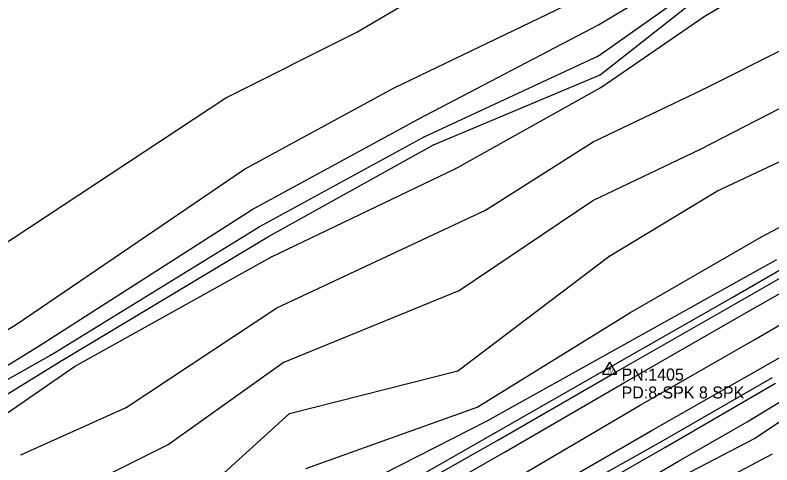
# Model space of a CAD drawing. Extents: x 1419505 to 1434054, y 1956910 to 1968644.
# Drawn here: x 1420049.5 to 1420365.7, y 1957354.8 to 1957542.8 of the extents above; entities that cross this region are included whole.
import ezdxf

# ---------------------------------------------------------------- set-up
doc = ezdxf.new("R2010")
doc.units = 0
for name, color, linetype in [('S_BREAKLINE', 7, 'Continuous'), ('S_DITCHLINE', 7, 'Continuous'), ('S_EDGE_PAVEMENT', 7, 'Continuous'), ('S_GRD_PT_SYM', 7, 'Continuous'), ('S_PAVEMENT_CROWN', 7, 'Continuous'), ('S_RDW_PT_SYM', 7, 'Continuous'), ('S_SECONDARY_CTL', 7, 'Continuous'), ('S_SECONDARY_CTL_ANNOT', 7, 'Continuous'), ('S_SHOULDER', 7, 'Continuous')]:
    doc.layers.add(name, color=color, linetype=linetype)

msp = doc.modelspace()

# ---------------------------------------------------------------- linework, layer by layer
at = {"layer": 'S_BREAKLINE'}
for p, q in [((1420192.3036, 1957535.6307), (1420290.752, 1957593.9905)), ((1420337.512, 1957542.1811), (1420418.3802, 1957590.8533)), ((1420293.3101, 1957538.7059), (1420365.5308, 1957582.2917)), ((1420336.8469, 1957511.6521), (1420430.621, 1957558.8422)), ((1420207.9006, 1957512.3842), (1420293.4111, 1957553.6049)), ((1420294.2222, 1957512.5972), (1420337.512, 1957542.1811)), ((1420335.9639, 1957486.7575), (1420440.9487, 1957541.147)), ((1420218.2373, 1957499.4904), (1420293.3101, 1957538.7059)), ((1420137.6381, 1957508.2519), (1420192.3036, 1957535.6307)), ((1420342.7853, 1957469.2664), (1420453.1484, 1957521.3868)), ((1420145.4236, 1957478.459), (1420207.9006, 1957512.3842)), ((1420233.6373, 1957478.746), (1420294.2222, 1957512.5972)), ((1420291.051, 1957489.8917), (1420336.8469, 1957511.6521)), ((1420022.9537, 1957432.616), (1420137.6381, 1957508.2519)), ((1420361.3455, 1957450.0972), (1420459.9679, 1957502.9656)), ((1420148.5408, 1957461.4819), (1420218.2373, 1957499.4904)), ((1420246.1361, 1957461.2649), (1420291.051, 1957489.8917)), ((1420290.916, 1957465.2691), (1420335.9639, 1957486.7575)), ((1420049.6074, 1957413.2558), (1420145.4236, 1957478.459)), ((1420156.6193, 1957441.7066), (1420233.6373, 1957478.746)), ((1420297.5794, 1957441.9206), (1420342.7853, 1957469.2664)), ((1420235.1024, 1957427.7497), (1420290.916, 1957465.2691)), ((1420059.534, 1957404.5312), (1420148.5408, 1957461.4819)), ((1420158.9444, 1957420.4363), (1420246.1361, 1957461.2649)), ((1420349.1857, 1957424.8305), (1420395.4067, 1957451.5023)), ((1420306.415, 1957418.4231), (1420361.3455, 1957450.0972)), ((1420074.324, 1957395.9717), (1420156.6193, 1957441.7066)), ((1420234.4453, 1957394.0666), (1420297.5794, 1957441.9206)), ((1420246.7721, 1957373.2022), (1420367.7909, 1957440.5896)), ((1420161.4816, 1957397.5688), (1420235.1024, 1957427.7497)), ((1420299.3175, 1957396.3807), (1420349.1857, 1957424.8305)), ((1420095.8914, 1957378.8396), (1420158.9444, 1957420.4363)), ((1420242.6288, 1957378.8926), (1420306.415, 1957418.4231)), ((1420024.8008, 1957398.6088), (1420049.6074, 1957413.2558)), ((1420021.9566, 1957381.6337), (1420059.534, 1957404.5312)), ((1420113.5025, 1957363.3696), (1420161.4816, 1957397.5688)), ((1420042.6259, 1957374.0053), (1420074.324, 1957395.9717)), ((1420164.2098, 1957376.2314), (1420234.4453, 1957394.0666)), ((1420249.9023, 1957368.1239), (1420299.3175, 1957396.3807)), ((1420320.9429, 1957362.0845), (1420367.2719, 1957388.9172)), ((1420355.4481, 1957372.7822), (1420378.5366, 1957386.9371)), ((1420358.5423, 1957365.7937), (1420382.7719, 1957382.3268)), ((1420051.9785, 1957359.0183), (1420095.8914, 1957378.8396)), ((1420171.0272, 1957353.2939), (1420242.6288, 1957378.8926)), ((1420127.9904, 1957343.5183), (1420164.2098, 1957376.2314)), ((1420178.1397, 1957338.305), (1420246.7721, 1957373.2022)), ((1420326.7323, 1957356.3401), (1420355.4481, 1957372.7822)), ((1420195.6758, 1957337.1809), (1420249.9023, 1957368.1239)), ((1420328.5074, 1957350.2417), (1420358.5423, 1957365.7937)), ((1420058.3479, 1957335.8728), (1420113.5025, 1957363.3696)), ((1420268.5635, 1957332.1216), (1420320.9429, 1957362.0845)), ((1420331.7176, 1957341.3011), (1420365.9838, 1957359.4623)), ((1420293.5931, 1957337.1349), (1420326.7323, 1957356.3401))]:
    msp.add_line(p, q, dxfattribs=at)
at = {"layer": 'S_DITCHLINE'}
for p, q in [((1420293.3431, 1957525.8091), (1420350.8378, 1957566.4497)), ((1420294.0512, 1957517.8655), (1420350.0148, 1957561.9554)), ((1420220.4114, 1957491.8719), (1420293.3431, 1957525.8091)), ((1420224.2847, 1957488.5137), (1420294.0512, 1957517.8655)), ((1420151.461, 1957454.2804), (1420220.4114, 1957491.8719)), ((1420155.4362, 1957450.2852), (1420224.2847, 1957488.5137)), ((1420064.5173, 1957400.875), (1420151.461, 1957454.2804)), ((1420068.3256, 1957397.9718), (1420155.4362, 1957450.2852)), ((1420022.8927, 1957377.2905), (1420064.5173, 1957400.875)), ((1420027.818, 1957373.1632), (1420068.3256, 1957397.9718))]:
    msp.add_line(p, q, dxfattribs=at)
at = {"layer": 'S_EDGE_PAVEMENT'}
for p, q in [((1420352.896, 1957417.206), (1420400.517, 1957444.3878)), ((1420364.1637, 1957396.8567), (1420413.3409, 1957425.0856)), ((1420304.2138, 1957389.2652), (1420352.896, 1957417.206)), ((1420316.0416, 1957369.443), (1420364.1637, 1957396.8567)), ((1420254.2766, 1957360.2364), (1420304.2138, 1957389.2652)), ((1420265.1203, 1957340.1861), (1420316.0416, 1957369.443)), ((1420200.5981, 1957329.8654), (1420254.2766, 1957360.2364))]:
    msp.add_line(p, q, dxfattribs=at)
at = {"layer": 'S_GRD_PT_SYM'}
for points in [[(1420337.512, 1957542.1811), (1420337.512, 1957542.2311), (1420337.512, 1957542.1811), (1420337.462, 1957542.1811), (1420337.512, 1957542.1811), (1420337.512, 1957542.1311), (1420337.512, 1957542.1811), (1420337.562, 1957542.1811)], [(1420293.3101, 1957538.7059), (1420293.3101, 1957538.7559), (1420293.3101, 1957538.7059), (1420293.2601, 1957538.7059), (1420293.3101, 1957538.7059), (1420293.3101, 1957538.6559), (1420293.3101, 1957538.7059), (1420293.3601, 1957538.7059)], [(1420192.3036, 1957535.6307), (1420192.3036, 1957535.6807), (1420192.3036, 1957535.6307), (1420192.2536, 1957535.6307), (1420192.3036, 1957535.6307), (1420192.3036, 1957535.5807), (1420192.3036, 1957535.6307), (1420192.3536, 1957535.6307)], [(1420293.3431, 1957525.8091), (1420293.3431, 1957525.8591), (1420293.3431, 1957525.8091), (1420293.2931, 1957525.8091), (1420293.3431, 1957525.8091), (1420293.3431, 1957525.7591), (1420293.3431, 1957525.8091), (1420293.3931, 1957525.8091)], [(1420294.0512, 1957517.8655), (1420294.0512, 1957517.9155), (1420294.0512, 1957517.8655), (1420294.0012, 1957517.8655), (1420294.0512, 1957517.8655), (1420294.0512, 1957517.8155), (1420294.0512, 1957517.8655), (1420294.1012, 1957517.8655)], [(1420207.9006, 1957512.3842), (1420207.9006, 1957512.4342), (1420207.9006, 1957512.3842), (1420207.8506, 1957512.3842), (1420207.9006, 1957512.3842), (1420207.9006, 1957512.3342), (1420207.9006, 1957512.3842), (1420207.9506, 1957512.3842)], [(1420294.2222, 1957512.5972), (1420294.2222, 1957512.6472), (1420294.2222, 1957512.5972), (1420294.1722, 1957512.5972), (1420294.2222, 1957512.5972), (1420294.2222, 1957512.5472), (1420294.2222, 1957512.5972), (1420294.2722, 1957512.5972)], [(1420336.8469, 1957511.6521), (1420336.8469, 1957511.7021), (1420336.8469, 1957511.6521), (1420336.7969, 1957511.6521), (1420336.8469, 1957511.6521), (1420336.8469, 1957511.6021), (1420336.8469, 1957511.6521), (1420336.8969, 1957511.6521)], [(1420137.6381, 1957508.2519), (1420137.6381, 1957508.3019), (1420137.6381, 1957508.2519), (1420137.5881, 1957508.2519), (1420137.6381, 1957508.2519), (1420137.6381, 1957508.2019), (1420137.6381, 1957508.2519), (1420137.6881, 1957508.2519)], [(1420218.2373, 1957499.4904), (1420218.2373, 1957499.5404), (1420218.2373, 1957499.4904), (1420218.1873, 1957499.4904), (1420218.2373, 1957499.4904), (1420218.2373, 1957499.4404), (1420218.2373, 1957499.4904), (1420218.2873, 1957499.4904)], [(1420220.4114, 1957491.8719), (1420220.4114, 1957491.9219), (1420220.4114, 1957491.8719), (1420220.3614, 1957491.8719), (1420220.4114, 1957491.8719), (1420220.4114, 1957491.8219), (1420220.4114, 1957491.8719), (1420220.4614, 1957491.8719)], [(1420291.051, 1957489.8917), (1420291.051, 1957489.9417), (1420291.051, 1957489.8917), (1420291.001, 1957489.8917), (1420291.051, 1957489.8917), (1420291.051, 1957489.8417), (1420291.051, 1957489.8917), (1420291.101, 1957489.8917)], [(1420224.2847, 1957488.5137), (1420224.2847, 1957488.5637), (1420224.2847, 1957488.5137), (1420224.2347, 1957488.5137), (1420224.2847, 1957488.5137), (1420224.2847, 1957488.4637), (1420224.2847, 1957488.5137), (1420224.3347, 1957488.5137)], [(1420335.9639, 1957486.7575), (1420335.9639, 1957486.8075), (1420335.9639, 1957486.7575), (1420335.9139, 1957486.7575), (1420335.9639, 1957486.7575), (1420335.9639, 1957486.7075), (1420335.9639, 1957486.7575), (1420336.0139, 1957486.7575)], [(1420145.4236, 1957478.459), (1420145.4236, 1957478.509), (1420145.4236, 1957478.459), (1420145.3736, 1957478.459), (1420145.4236, 1957478.459), (1420145.4236, 1957478.409), (1420145.4236, 1957478.459), (1420145.4736, 1957478.459)], [(1420233.6373, 1957478.746), (1420233.6373, 1957478.796), (1420233.6373, 1957478.746), (1420233.5873, 1957478.746), (1420233.6373, 1957478.746), (1420233.6373, 1957478.696), (1420233.6373, 1957478.746), (1420233.6873, 1957478.746)], [(1420342.7853, 1957469.2664), (1420342.7853, 1957469.3164), (1420342.7853, 1957469.2664), (1420342.7353, 1957469.2664), (1420342.7853, 1957469.2664), (1420342.7853, 1957469.2164), (1420342.7853, 1957469.2664), (1420342.8353, 1957469.2664)], [(1420290.916, 1957465.2691), (1420290.916, 1957465.3191), (1420290.916, 1957465.2691), (1420290.866, 1957465.2691), (1420290.916, 1957465.2691), (1420290.916, 1957465.2191), (1420290.916, 1957465.2691), (1420290.966, 1957465.2691)], [(1420148.5408, 1957461.4819), (1420148.5408, 1957461.5319), (1420148.5408, 1957461.4819), (1420148.4908, 1957461.4819), (1420148.5408, 1957461.4819), (1420148.5408, 1957461.4319), (1420148.5408, 1957461.4819), (1420148.5908, 1957461.4819)], [(1420246.1361, 1957461.2649), (1420246.1361, 1957461.3149), (1420246.1361, 1957461.2649), (1420246.0861, 1957461.2649), (1420246.1361, 1957461.2649), (1420246.1361, 1957461.2149), (1420246.1361, 1957461.2649), (1420246.1861, 1957461.2649)], [(1420151.461, 1957454.2804), (1420151.461, 1957454.3304), (1420151.461, 1957454.2804), (1420151.411, 1957454.2804), (1420151.461, 1957454.2804), (1420151.461, 1957454.2304), (1420151.461, 1957454.2804), (1420151.511, 1957454.2804)], [(1420155.4362, 1957450.2852), (1420155.4362, 1957450.3352), (1420155.4362, 1957450.2852), (1420155.3862, 1957450.2852), (1420155.4362, 1957450.2852), (1420155.4362, 1957450.2352), (1420155.4362, 1957450.2852), (1420155.4862, 1957450.2852)], [(1420361.3455, 1957450.0972), (1420361.3455, 1957450.1472), (1420361.3455, 1957450.0972), (1420361.2955, 1957450.0972), (1420361.3455, 1957450.0972), (1420361.3455, 1957450.0472), (1420361.3455, 1957450.0972), (1420361.3955, 1957450.0972)], [(1420156.6193, 1957441.7066), (1420156.6193, 1957441.7566), (1420156.6193, 1957441.7066), (1420156.5693, 1957441.7066), (1420156.6193, 1957441.7066), (1420156.6193, 1957441.6566), (1420156.6193, 1957441.7066), (1420156.6693, 1957441.7066)], [(1420297.5794, 1957441.9206), (1420297.5794, 1957441.9706), (1420297.5794, 1957441.9206), (1420297.5294, 1957441.9206), (1420297.5794, 1957441.9206), (1420297.5794, 1957441.8706), (1420297.5794, 1957441.9206), (1420297.6294, 1957441.9206)], [(1420235.1024, 1957427.7497), (1420235.1024, 1957427.7997), (1420235.1024, 1957427.7497), (1420235.0524, 1957427.7497), (1420235.1024, 1957427.7497), (1420235.1024, 1957427.6997), (1420235.1024, 1957427.7497), (1420235.1524, 1957427.7497)], [(1420349.1857, 1957424.8305), (1420349.1857, 1957424.8805), (1420349.1857, 1957424.8305), (1420349.1357, 1957424.8305), (1420349.1857, 1957424.8305), (1420349.1857, 1957424.7805), (1420349.1857, 1957424.8305), (1420349.2357, 1957424.8305)], [(1420158.9444, 1957420.4363), (1420158.9444, 1957420.4863), (1420158.9444, 1957420.4363), (1420158.8944, 1957420.4363), (1420158.9444, 1957420.4363), (1420158.9444, 1957420.3863), (1420158.9444, 1957420.4363), (1420158.9944, 1957420.4363)], [(1420306.415, 1957418.4231), (1420306.415, 1957418.4731), (1420306.415, 1957418.4231), (1420306.365, 1957418.4231), (1420306.415, 1957418.4231), (1420306.415, 1957418.3731), (1420306.415, 1957418.4231), (1420306.465, 1957418.4231)], [(1420049.6074, 1957413.2558), (1420049.6074, 1957413.3058), (1420049.6074, 1957413.2558), (1420049.5574, 1957413.2558), (1420049.6074, 1957413.2558), (1420049.6074, 1957413.2058), (1420049.6074, 1957413.2558), (1420049.6574, 1957413.2558)], [(1420059.534, 1957404.5312), (1420059.534, 1957404.5812), (1420059.534, 1957404.5312), (1420059.484, 1957404.5312), (1420059.534, 1957404.5312), (1420059.534, 1957404.4812), (1420059.534, 1957404.5312), (1420059.584, 1957404.5312)], [(1420064.5173, 1957400.875), (1420064.5173, 1957400.925), (1420064.5173, 1957400.875), (1420064.4673, 1957400.875), (1420064.5173, 1957400.875), (1420064.5173, 1957400.825), (1420064.5173, 1957400.875), (1420064.5673, 1957400.875)], [(1420068.3256, 1957397.9718), (1420068.3256, 1957398.0218), (1420068.3256, 1957397.9718), (1420068.2756, 1957397.9718), (1420068.3256, 1957397.9718), (1420068.3256, 1957397.9218), (1420068.3256, 1957397.9718), (1420068.3756, 1957397.9718)], [(1420161.4816, 1957397.5688), (1420161.4816, 1957397.6188), (1420161.4816, 1957397.5688), (1420161.4316, 1957397.5688), (1420161.4816, 1957397.5688), (1420161.4816, 1957397.5188), (1420161.4816, 1957397.5688), (1420161.5316, 1957397.5688)], [(1420074.324, 1957395.9717), (1420074.324, 1957396.0217), (1420074.324, 1957395.9717), (1420074.274, 1957395.9717), (1420074.324, 1957395.9717), (1420074.324, 1957395.9217), (1420074.324, 1957395.9717), (1420074.374, 1957395.9717)], [(1420234.4453, 1957394.0666), (1420234.4453, 1957394.1166), (1420234.4453, 1957394.0666), (1420234.3953, 1957394.0666), (1420234.4453, 1957394.0666), (1420234.4453, 1957394.0166), (1420234.4453, 1957394.0666), (1420234.4953, 1957394.0666)], [(1420299.3175, 1957396.3807), (1420299.3175, 1957396.4307), (1420299.3175, 1957396.3807), (1420299.2675, 1957396.3807), (1420299.3175, 1957396.3807), (1420299.3175, 1957396.3307), (1420299.3175, 1957396.3807), (1420299.3675, 1957396.3807)], [(1420095.8914, 1957378.8396), (1420095.8914, 1957378.8896), (1420095.8914, 1957378.8396), (1420095.8414, 1957378.8396), (1420095.8914, 1957378.8396), (1420095.8914, 1957378.7896), (1420095.8914, 1957378.8396), (1420095.9414, 1957378.8396)], [(1420242.6288, 1957378.8926), (1420242.6288, 1957378.9426), (1420242.6288, 1957378.8926), (1420242.5788, 1957378.8926), (1420242.6288, 1957378.8926), (1420242.6288, 1957378.8426), (1420242.6288, 1957378.8926), (1420242.6788, 1957378.8926)], [(1420164.2098, 1957376.2314), (1420164.2098, 1957376.2814), (1420164.2098, 1957376.2314), (1420164.1598, 1957376.2314), (1420164.2098, 1957376.2314), (1420164.2098, 1957376.1814), (1420164.2098, 1957376.2314), (1420164.2598, 1957376.2314)], [(1420246.7721, 1957373.2022), (1420246.7721, 1957373.2522), (1420246.7721, 1957373.2022), (1420246.7221, 1957373.2022), (1420246.7721, 1957373.2022), (1420246.7721, 1957373.1522), (1420246.7721, 1957373.2022), (1420246.8221, 1957373.2022)], [(1420355.4481, 1957372.7822), (1420355.4481, 1957372.8322), (1420355.4481, 1957372.7822), (1420355.3981, 1957372.7822), (1420355.4481, 1957372.7822), (1420355.4481, 1957372.7322), (1420355.4481, 1957372.7822), (1420355.4981, 1957372.7822)], [(1420249.9023, 1957368.1239), (1420249.9023, 1957368.1739), (1420249.9023, 1957368.1239), (1420249.8523, 1957368.1239), (1420249.9023, 1957368.1239), (1420249.9023, 1957368.0739), (1420249.9023, 1957368.1239), (1420249.9523, 1957368.1239)], [(1420358.5423, 1957365.7937), (1420358.5423, 1957365.8437), (1420358.5423, 1957365.7937), (1420358.4923, 1957365.7937), (1420358.5423, 1957365.7937), (1420358.5423, 1957365.7437), (1420358.5423, 1957365.7937), (1420358.5923, 1957365.7937)], [(1420113.5025, 1957363.3696), (1420113.5025, 1957363.4196), (1420113.5025, 1957363.3696), (1420113.4525, 1957363.3696), (1420113.5025, 1957363.3696), (1420113.5025, 1957363.3196), (1420113.5025, 1957363.3696), (1420113.5525, 1957363.3696)], [(1420320.9429, 1957362.0845), (1420320.9429, 1957362.1345), (1420320.9429, 1957362.0845), (1420320.8929, 1957362.0845), (1420320.9429, 1957362.0845), (1420320.9429, 1957362.0345), (1420320.9429, 1957362.0845), (1420320.9929, 1957362.0845)], [(1420051.9785, 1957359.0183), (1420051.9785, 1957359.0683), (1420051.9785, 1957359.0183), (1420051.9285, 1957359.0183), (1420051.9785, 1957359.0183), (1420051.9785, 1957358.9683), (1420051.9785, 1957359.0183), (1420052.0285, 1957359.0183)], [(1420326.7323, 1957356.3401), (1420326.7323, 1957356.3901), (1420326.7323, 1957356.3401), (1420326.6823, 1957356.3401), (1420326.7323, 1957356.3401), (1420326.7323, 1957356.2901), (1420326.7323, 1957356.3401), (1420326.7823, 1957356.3401)]]:
    msp.add_lwpolyline(points, dxfattribs=at)
at = {"layer": 'S_PAVEMENT_CROWN'}
for p, q in [((1420358.3463, 1957407.0474), (1420406.9165, 1957435.2332)), ((1420310.6932, 1957379.7186), (1420358.3463, 1957407.0474)), ((1420259.3559, 1957349.4937), (1420310.6932, 1957379.7186))]:
    msp.add_line(p, q, dxfattribs=at)
at = {"layer": 'S_RDW_PT_SYM'}
for points in [[(1420350.7198, 1957422.2894), (1420350.7198, 1957422.3394), (1420350.7198, 1957422.2894), (1420350.6698, 1957422.2894), (1420350.7198, 1957422.2894), (1420350.7198, 1957422.2394), (1420350.7198, 1957422.2894), (1420350.7698, 1957422.2894)], [(1420352.896, 1957417.206), (1420352.896, 1957417.256), (1420352.896, 1957417.206), (1420352.846, 1957417.206), (1420352.896, 1957417.206), (1420352.896, 1957417.156), (1420352.896, 1957417.206), (1420352.946, 1957417.206)], [(1420358.3463, 1957407.0474), (1420358.3463, 1957407.0974), (1420358.3463, 1957407.0474), (1420358.2963, 1957407.0474), (1420358.3463, 1957407.0474), (1420358.3463, 1957406.9974), (1420358.3463, 1957407.0474), (1420358.3963, 1957407.0474)], [(1420364.1637, 1957396.8567), (1420364.1637, 1957396.9067), (1420364.1637, 1957396.8567), (1420364.1137, 1957396.8567), (1420364.1637, 1957396.8567), (1420364.1637, 1957396.8067), (1420364.1637, 1957396.8567), (1420364.2137, 1957396.8567)], [(1420300.9426, 1957393.8375), (1420300.9426, 1957393.8875), (1420300.9426, 1957393.8375), (1420300.8926, 1957393.8375), (1420300.9426, 1957393.8375), (1420300.9426, 1957393.7875), (1420300.9426, 1957393.8375), (1420300.9926, 1957393.8375)], [(1420304.2138, 1957389.2652), (1420304.2138, 1957389.3152), (1420304.2138, 1957389.2652), (1420304.1638, 1957389.2652), (1420304.2138, 1957389.2652), (1420304.2138, 1957389.2152), (1420304.2138, 1957389.2652), (1420304.2638, 1957389.2652)], [(1420310.6932, 1957379.7186), (1420310.6932, 1957379.7686), (1420310.6932, 1957379.7186), (1420310.6432, 1957379.7186), (1420310.6932, 1957379.7186), (1420310.6932, 1957379.6686), (1420310.6932, 1957379.7186), (1420310.7432, 1957379.7186)], [(1420316.0416, 1957369.443), (1420316.0416, 1957369.493), (1420316.0416, 1957369.443), (1420315.9916, 1957369.443), (1420316.0416, 1957369.443), (1420316.0416, 1957369.393), (1420316.0416, 1957369.443), (1420316.0916, 1957369.443)], [(1420251.4994, 1957365.3437), (1420251.4994, 1957365.3937), (1420251.4994, 1957365.3437), (1420251.4494, 1957365.3437), (1420251.4994, 1957365.3437), (1420251.4994, 1957365.2937), (1420251.4994, 1957365.3437), (1420251.5494, 1957365.3437)], [(1420319.3778, 1957364.4636), (1420319.3778, 1957364.5136), (1420319.3778, 1957364.4636), (1420319.3278, 1957364.4636), (1420319.3778, 1957364.4636), (1420319.3778, 1957364.4136), (1420319.3778, 1957364.4636), (1420319.4278, 1957364.4636)], [(1420254.2766, 1957360.2364), (1420254.2766, 1957360.2864), (1420254.2766, 1957360.2364), (1420254.2266, 1957360.2364), (1420254.2766, 1957360.2364), (1420254.2766, 1957360.1864), (1420254.2766, 1957360.2364), (1420254.3266, 1957360.2364)]]:
    msp.add_lwpolyline(points, dxfattribs=at)
at = {"layer": 'S_SECONDARY_CTL'}
for p, q in [((1420297.9304, 1957397.6897), (1420294.9204, 1957392.7358)), ((1420297.9304, 1957397.6897), (1420300.8777, 1957392.7358)), ((1420294.9204, 1957392.7358), (1420300.8777, 1957392.7358))]:
    msp.add_line(p, q, dxfattribs=at)
for radius in [0.3111, 0.1827, 0.1033]:
    msp.add_circle((1420297.9304, 1957395.0796), radius, dxfattribs=at)
at = {"layer": 'S_SHOULDER'}
for p, q in [((1420350.7198, 1957422.2894), (1420396.9288, 1957448.9981)), ((1420300.9426, 1957393.8375), (1420350.7198, 1957422.2894)), ((1420251.4994, 1957365.3437), (1420300.9426, 1957393.8375)), ((1420319.3778, 1957364.4636), (1420366.0558, 1957391.3334)), ((1420196.9439, 1957334.4397), (1420251.4994, 1957365.3437)), ((1420267.2064, 1957335.2758), (1420319.3778, 1957364.4636))]:
    msp.add_line(p, q, dxfattribs=at)

# ---------------------------------------------------------------- texts
at = {"layer": 'S_SECONDARY_CTL'}
msp.add_text('TV', height=1.5, rotation=360, dxfattribs=at).set_placement((1420296.7257, 1957393.0683))
at = {"layer": 'S_SECONDARY_CTL_ANNOT'}
for s, p in [('PN:1405', (1420302.9304, 1957390.0796)), ('PD:8-SPK 8 SPK', (1420302.9304, 1957382.5796))]:
    msp.add_text(s, height=5, dxfattribs=at).set_placement(p)

doc.saveas('drawing.dxf')
